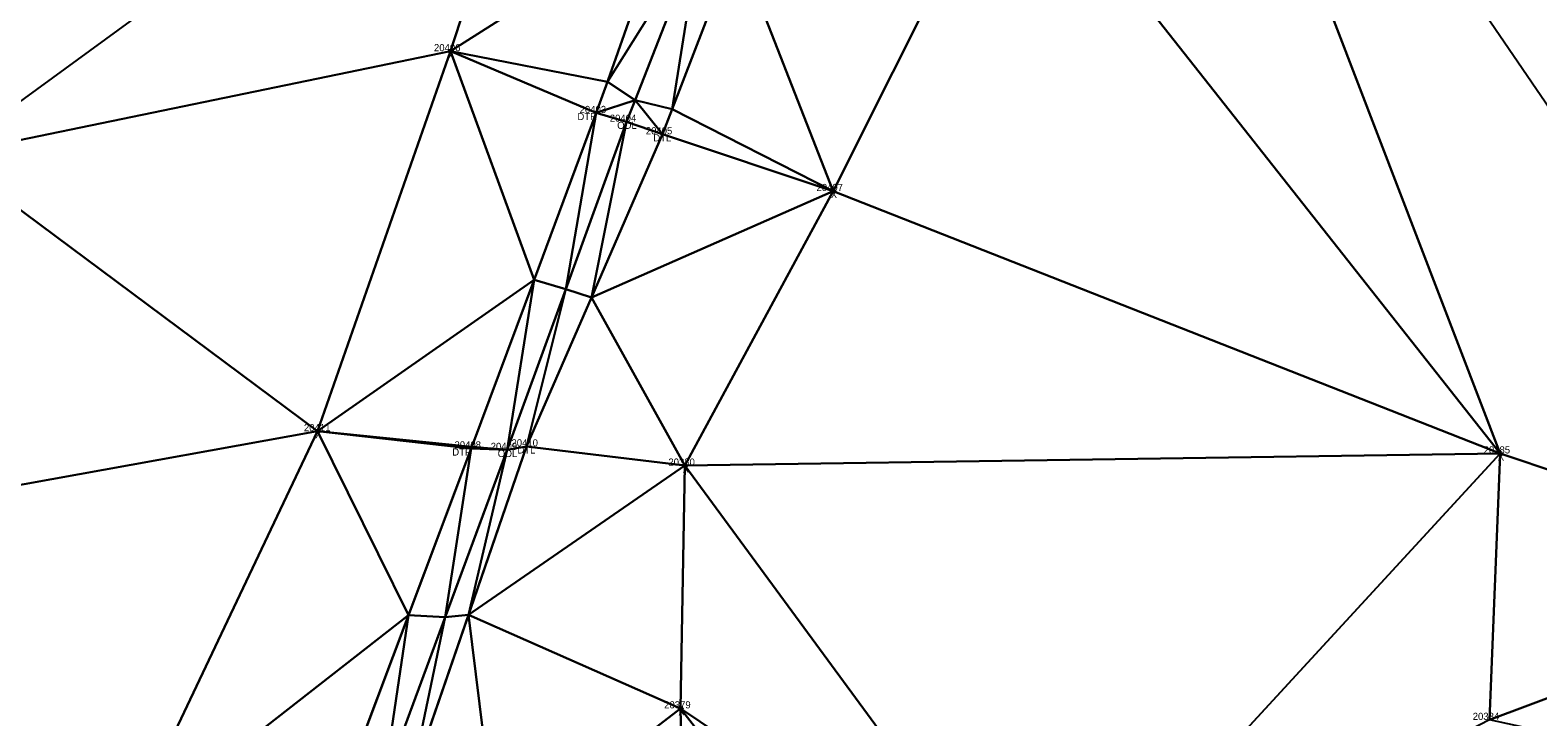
# Model space of a CAD drawing. Extents: x 1966740 to 1969291, y 1117379 to 1118460.
# Drawn here: x 1968331 to 1968542.7, y 1117976 to 1118072.4 of the extents above; entities that cross this region are included whole.
import ezdxf

# ---------------------------------------------------------------- set-up
doc = ezdxf.new("R2010")
doc.units = 0
for name, color, linetype in [('Level 10', 7, 'Continuous'), ('Level 30', 7, 'Continuous'), ('Level 35', 7, 'Continuous'), ('Level 50', 7, 'Continuous'), ('Level 52', 7, 'Continuous'), ('Level 56', 7, 'Continuous'), ('Level 6', 7, 'Continuous'), ('Level 60', 7, 'Continuous'), ('Level 61', 7, 'Continuous'), ('Level 62', 7, 'Continuous')]:
    doc.layers.add(name, color=color, linetype=linetype)

msp = doc.modelspace()

# ---------------------------------------------------------------- linework, layer by layer
at = {"layer": 'Level 10'}
for points in [[(1968464.83, 1118211.88), (1968447.38, 1118161.72), (1968428.66, 1118112.3), (1968410.49, 1118060.76), (1968392.92, 1118013.68), (1968370.86, 1117955.02), (1968371.01, 1117946.77)], [(1968473.95, 1118208.63), (1968457.08, 1118158.03), (1968439.1, 1118107.96), (1968419.78, 1118057.77), (1968400.7, 1118013.97), (1968380.14, 1117954.31), (1968378.68, 1117946.52)]]:
    msp.add_lwpolyline(points, dxfattribs=at)
at = {"layer": 'Level 30'}
for centre in [(1968390.02, 1118069.43), (1968443.75, 1118049.81), (1968371.35, 1118016.1), (1968537.39, 1118012.98), (1968422.92, 1118011.27), (1968422.32, 1117977.2)]:
    msp.add_circle(centre, 0.25, dxfattribs=at)
at = {"layer": 'Level 35'}
for points in [[(1968468.83, 1118099.84), (1968485.97, 1118146.88), (1968537.39, 1118012.98)], [(1968485.97, 1118146.88), (1968589.34, 1117995.59), (1968537.39, 1118012.98)], [(1968319.25, 1118054.83), (1968405.82, 1118118), (1968390.02, 1118069.43)], [(1968390.02, 1118069.43), (1968405.82, 1118118), (1968420.35, 1118088.72)], [(1968430.12, 1118084.63), (1968468.83, 1118099.84), (1968443.75, 1118049.81)], [(1968443.75, 1118049.81), (1968468.83, 1118099.84), (1968537.39, 1118012.98)], [(1968390.02, 1118069.43), (1968420.35, 1118088.72), (1968412.04, 1118065.14)], [(1968412.04, 1118065.14), (1968420.35, 1118088.72), (1968425.04, 1118085.82)], [(1968412.04, 1118065.14), (1968425.04, 1118085.82), (1968415.93, 1118062.54)], [(1968415.93, 1118062.54), (1968425.04, 1118085.82), (1968421.14, 1118061.3)], [(1968421.14, 1118061.3), (1968425.04, 1118085.82), (1968430.12, 1118084.63)], [(1968421.14, 1118061.3), (1968430.12, 1118084.63), (1968443.75, 1118049.81)], [(1968319.25, 1118054.83), (1968390.02, 1118069.43), (1968371.35, 1118016.1)], [(1968371.35, 1118016.1), (1968390.02, 1118069.43), (1968401.75, 1118037.34)], [(1968390.02, 1118069.43), (1968412.04, 1118065.14), (1968410.49, 1118060.76)], [(1968390.02, 1118069.43), (1968410.49, 1118060.76), (1968401.75, 1118037.34)], [(1968410.49, 1118060.76), (1968412.04, 1118065.14), (1968415.93, 1118062.54)], [(1968410.49, 1118060.76), (1968415.93, 1118062.54), (1968414.75, 1118059.53)], [(1968414.75, 1118059.53), (1968415.93, 1118062.54), (1968419.78, 1118057.77)], [(1968415.93, 1118062.54), (1968421.14, 1118061.3), (1968419.78, 1118057.77)], [(1968419.78, 1118057.77), (1968421.14, 1118061.3), (1968443.75, 1118049.81)], [(1968401.75, 1118037.34), (1968410.49, 1118060.76), (1968406.19, 1118036.04)], [(1968406.19, 1118036.04), (1968410.49, 1118060.76), (1968414.75, 1118059.53)], [(1968406.19, 1118036.04), (1968414.75, 1118059.53), (1968409.8, 1118034.85)], [(1968409.8, 1118034.85), (1968414.75, 1118059.53), (1968419.78, 1118057.77)], [(1968409.8, 1118034.85), (1968419.78, 1118057.77), (1968443.75, 1118049.81)], [(1968296.69, 1118002.64), (1968319.25, 1118054.83), (1968371.35, 1118016.1)], [(1968409.8, 1118034.85), (1968443.75, 1118049.81), (1968422.92, 1118011.27)], [(1968422.92, 1118011.27), (1968443.75, 1118049.81), (1968537.39, 1118012.98)], [(1968371.35, 1118016.1), (1968401.75, 1118037.34), (1968393.01, 1118013.92)], [(1968393.01, 1118013.92), (1968401.75, 1118037.34), (1968397.98, 1118013.47)], [(1968397.98, 1118013.47), (1968401.75, 1118037.34), (1968406.19, 1118036.04)], [(1968397.98, 1118013.47), (1968406.19, 1118036.04), (1968400.7, 1118013.97)], [(1968400.7, 1118013.97), (1968406.19, 1118036.04), (1968409.8, 1118034.85)], [(1968400.7, 1118013.97), (1968409.8, 1118034.85), (1968422.92, 1118011.27)], [(1968296.69, 1118002.64), (1968371.35, 1118016.1), (1968344.33, 1117959.2)], [(1968344.33, 1117959.2), (1968371.35, 1118016.1), (1968384.12, 1117990.28)], [(1968371.35, 1118016.1), (1968393.01, 1118013.92), (1968392.92, 1118013.68)], [(1968371.35, 1118016.1), (1968392.92, 1118013.68), (1968384.12, 1117990.28)], [(1968384.12, 1117990.28), (1968392.92, 1118013.68), (1968389.29, 1117990.02)], [(1968389.29, 1117990.02), (1968392.92, 1118013.68), (1968397.98, 1118013.47)], [(1968389.29, 1117990.02), (1968397.98, 1118013.47), (1968392.56, 1117990.33)], [(1968392.56, 1117990.33), (1968397.98, 1118013.47), (1968400.7, 1118013.97)], [(1968392.56, 1117990.33), (1968400.7, 1118013.97), (1968422.92, 1118011.27)], [(1968392.92, 1118013.68), (1968393.01, 1118013.92), (1968397.98, 1118013.47)], [(1968422.92, 1118011.27), (1968537.39, 1118012.98), (1968473.03, 1117943.08)], [(1968473.03, 1117943.08), (1968537.39, 1118012.98), (1968535.88, 1117975.58)], [(1968535.88, 1117975.58), (1968537.39, 1118012.98), (1968589.34, 1117995.59)], [(1968392.56, 1117990.33), (1968422.92, 1118011.27), (1968422.32, 1117977.2)], [(1968422.32, 1117977.2), (1968422.92, 1118011.27), (1968473.03, 1117943.08)], [(1968535.88, 1117975.58), (1968589.34, 1117995.59), (1968586.56, 1117964.56)], [(1968344.33, 1117959.2), (1968384.12, 1117990.28), (1968375.32, 1117966.88)], [(1968375.32, 1117966.88), (1968384.12, 1117990.28), (1968380.61, 1117966.58)], [(1968380.61, 1117966.58), (1968384.12, 1117990.28), (1968389.29, 1117990.02)], [(1968380.61, 1117966.58), (1968389.29, 1117990.02), (1968384.41, 1117966.7)], [(1968384.41, 1117966.7), (1968389.29, 1117990.02), (1968392.56, 1117990.33)], [(1968384.41, 1117966.7), (1968392.56, 1117990.33), (1968396.63, 1117957.39)], [(1968392.56, 1117990.33), (1968422.32, 1117977.2), (1968396.63, 1117957.39)], [(1968396.63, 1117957.39), (1968422.32, 1117977.2), (1968423.07, 1117945.03)], [(1968422.32, 1117977.2), (1968473.03, 1117943.08), (1968448.05, 1117944.05)], [(1968422.32, 1117977.2), (1968448.05, 1117944.05), (1968423.07, 1117945.03)]]:
    msp.add_lwpolyline(points, close=True, dxfattribs=at)
at = {"layer": 'Level 50'}
for centre in [(1968410.49, 1118060.76), (1968414.75, 1118059.53), (1968419.78, 1118057.77), (1968392.92, 1118013.68), (1968397.98, 1118013.47), (1968400.7, 1118013.97)]:
    msp.add_circle(centre, 0.001, dxfattribs=at)
at = {"layer": 'Level 6'}
msp.add_lwpolyline([(1968468.44, 1118210.37), (1968452.83, 1118159.99), (1968434.15, 1118109.1), (1968414.75, 1118059.53), (1968397.98, 1118013.47), (1968375.81, 1117953.62), (1968373.17, 1117942.71)], dxfattribs=at)

# ---------------------------------------------------------------- texts
at = {"layer": 'Level 52'}
for s, p in [('20406', (1968387.7, 1118069.43)), ('20407', (1968441.4, 1118049.81)), ('20411', (1968369.44, 1118016.1)), ('20385', (1968535.07, 1118012.98)), ('20380', (1968420.61, 1118011.27)), ('20379', (1968420.02, 1117977.2)), ('20384', (1968533.54, 1117975.58))]:
    msp.add_text(s, height=1, dxfattribs=at).set_placement(p)
at = {"layer": 'Level 56'}
for s, p in [('20404', (1968412.38, 1118059.53)), ('ODL', (1968413.42, 1118058.53)), ('20409', (1968395.66, 1118013.47)), ('ODL', (1968396.65, 1118012.47))]:
    msp.add_text(s, height=1, dxfattribs=at).set_placement(p)
at = {"layer": 'Level 60'}
for s, p in [('DTR', (1968407.84, 1118059.76)), ('DTL', (1968418.5, 1118056.77)), ('DTR', (1968390.27, 1118012.68)), ('DTL', (1968399.42, 1118012.97))]:
    msp.add_text(s, height=1, dxfattribs=at).set_placement(p)
at = {"layer": 'Level 61'}
for s, p in [('20403', (1968408.15, 1118060.76)), ('20405', (1968417.44, 1118057.77)), ('20408', (1968390.58, 1118013.68)), ('20410', (1968398.58, 1118013.97))]:
    msp.add_text(s, height=1, dxfattribs=at).set_placement(p)
at = {"layer": 'Level 62'}
for p in [(1968389.68, 1118068.43), (1968443.41, 1118048.81), (1968371.01, 1118015.1), (1968537.06, 1118011.98), (1968422.59, 1118010.27), (1968421.99, 1117976.2)]:
    msp.add_text('X', height=1, dxfattribs=at).set_placement(p)

doc.saveas('drawing.dxf')
